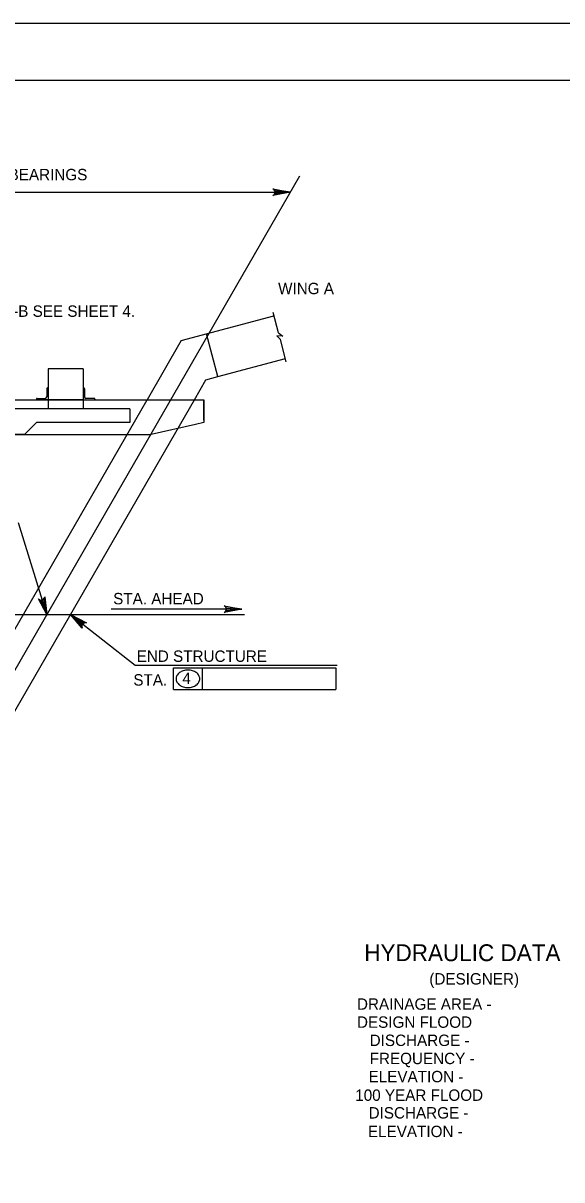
# Model space of a CAD drawing. Extents: x 638268 to 640277, y 295465 to 298435.
# Drawn here: x 638750 to 638891.9, y 298131.1 to 298435.5 of the extents above; entities that cross this region are included whole.
import ezdxf

# ---------------------------------------------------------------- set-up
doc = ezdxf.new("R2010")
doc.units = 0
for name, color, linetype in [('2', 7, 'Continuous'), ('3', 7, 'Continuous'), ('4', 7, 'Continuous'), ('PLT-BNDY', 7, 'Continuous')]:
    doc.layers.add(name, color=color, linetype=linetype)

msp = doc.modelspace()

# ---------------------------------------------------------------- linework, layer by layer
at = {"layer": '2'}
for p, q in [((638475.46, 298420.46), (639261.46, 298420.46)), ((638791.62, 298351.94), (638816.03, 298358.48)), ((638801.25, 298342.47), (638798.24, 298353.71)), ((638791.62, 298351.94), (638782.63, 298336.37)), ((638801.25, 298342.47), (638819.04, 298347.24)), ((638765.78, 298344.46), (638756.54, 298344.46)), ((638756.54, 298344.46), (638756.54, 298333.98)), ((638765.78, 298344.46), (638765.78, 298333.98)), ((638795.06, 298336.37), (638798.1, 298341.63)), ((638798.1, 298341.63), (638801.25, 298342.47)), ((638756.18, 298339.28), (638756.18, 298337.1)), ((638756.36, 298339.46), (638756.54, 298339.46)), ((638756.54, 298339.46), (638756.54, 298336.37)), ((638765.96, 298339.46), (638765.78, 298339.46)), ((638765.78, 298339.46), (638765.78, 298336.37)), ((638766.14, 298339.28), (638766.14, 298337.1)), ((638650.43, 298336.37), (638797.52, 298336.37)), ((638718.45, 298225.2), (638782.63, 298336.37)), ((638730.88, 298225.2), (638795.06, 298336.37)), ((638753.45, 298336.55), (638753.45, 298336.37)), ((638756.54, 298336.37), (638753.45, 298336.37)), ((638753.63, 298336.73), (638755.81, 298336.73)), ((638765.78, 298336.37), (638756.54, 298336.37)), ((638765.78, 298336.37), (638768.87, 298336.37)), ((638768.69, 298336.73), (638766.5, 298336.73)), ((638768.87, 298336.55), (638768.87, 298336.37)), ((638797.52, 298330.99), (638797.52, 298336.37)), ((638797.52, 298336.37), (638797.52, 298330.34)), ((638778.1, 298333.98), (638650.25, 298333.98)), ((638778.1, 298333.98), (638778.1, 298330.34)), ((638750.37, 298327.25), (638753.46, 298330.34)), ((638778.1, 298330.34), (638753.46, 298330.34)), ((638795.35, 298329.86), (638783.67, 298327.25)), ((638797.52, 298330.34), (638795.35, 298329.86)), ((638632.81, 298327.25), (638783.67, 298327.25)), ((638750.37, 298327.25), (638729.59, 298327.25))]:
    msp.add_line(p, q, dxfattribs=at)
for centre, radius, start, end in [((638756.36, 298339.28), 0.182, 90, 179.9984), ((638765.96, 298339.28), 0.182, 0.0016, 90), ((638753.63, 298336.55), 0.182, 90, 179.9984), ((638755.81, 298337.1), 0.364, 270, 359.9984), ((638766.5, 298337.1), 0.364, 180.0016, 270), ((638768.69, 298336.55), 0.182, 0.0016, 90)]:
    msp.add_arc(centre, radius, start, end, dxfattribs=at)
at = {"layer": '3'}
for p, q in [((638691.03, 298166.95), (638822.86, 298395.29)), ((638817.24, 298353.94), (638815.81, 298359.28)), ((638816.78, 298353.21), (638817.71, 298352.2)), ((638818.34, 298353.12), (638816.78, 298353.21)), ((638817.24, 298353.94), (638818.34, 298353.12)), ((638819.27, 298346.37), (638817.71, 298352.2))]:
    msp.add_line(p, q, dxfattribs=at)
at = {"layer": '4'}
for p, q in [((638628.98, 298391), (638820.39, 298391)), ((638756.2, 298279.83), (638748.74, 298304.01)), ((638807.54, 298281.23), (638773.18, 298281.23)), ((638523.29, 298279.83), (638808.3, 298279.83)), ((638762.42, 298279.83), (638779.49, 298266.49)), ((638779.49, 298266.49), (638832.67, 298266.49)), ((638789.59, 298265.87), (638797.17, 298265.87)), ((638789.59, 298260.11), (638789.59, 298265.87)), ((638797.17, 298260.11), (638797.17, 298265.87)), ((638797.17, 298265.87), (638832.35, 298265.87)), ((638832.35, 298265.87), (638832.35, 298260.11)), ((638789.59, 298260.11), (638832.35, 298260.11))]:
    msp.add_line(p, q, dxfattribs=at)
for points in [[(638820.39, 298391), (638815.73, 298390.12), (638816.08, 298390.37), (638816.27, 298390.68), (638816.32, 298391), (638816.27, 298391.31), (638816.08, 298391.62), (638815.73, 298391.87), (638820.39, 298391), (638816.08, 298391.62), (638816.27, 298391.31), (638820.39, 298391), (638816.32, 298391), (638816.27, 298390.68), (638820.39, 298391), (638816.08, 298390.37)], [(638756.2, 298279.83), (638753.99, 298284.03), (638754.34, 298283.76), (638754.69, 298283.67), (638755.01, 298283.71), (638755.29, 298283.86), (638755.53, 298284.12), (638755.66, 298284.54), (638756.2, 298279.83), (638755.53, 298284.12), (638755.29, 298283.86), (638756.2, 298279.83), (638755.01, 298283.71), (638754.69, 298283.67), (638756.2, 298279.83), (638754.34, 298283.76)], [(638807.54, 298281.23), (638802.88, 298280.36), (638803.24, 298280.61), (638803.43, 298280.92), (638803.48, 298281.23), (638803.43, 298281.55), (638803.24, 298281.86), (638802.88, 298282.11), (638807.54, 298281.23), (638803.24, 298281.86), (638803.43, 298281.55), (638807.54, 298281.23), (638803.48, 298281.23), (638803.43, 298280.92), (638807.54, 298281.23), (638803.24, 298280.61)], [(638762.42, 298279.83), (638766.63, 298277.65), (638766.19, 298277.67), (638765.86, 298277.54), (638765.62, 298277.33), (638765.47, 298277.05), (638765.43, 298276.69), (638765.55, 298276.27), (638762.42, 298279.83), (638765.43, 298276.69), (638765.47, 298277.05), (638762.42, 298279.83), (638765.62, 298277.33), (638765.86, 298277.54), (638762.42, 298279.83), (638766.19, 298277.67)]]:
    msp.add_lwpolyline(points, dxfattribs=at)
msp.add_lwpolyline([(638755.8, 298282.8), (638754.86, 298282.51), (638756.2, 298279.83)], close=True, dxfattribs=at)
for centre, radius, start, end in [((638793.08, 298261.96), 3.23, 106.9552, 126.3544), ((638793.37, 298261.02), 4.22, 90, 106.9552), ((638793.37, 298261.02), 4.22, 73.0448, 90), ((638793.66, 298261.96), 3.23, 53.6456, 73.0448), ((638791.97, 298262.94), 1.71, 150.6308, 180), ((638791.97, 298262.94), 1.71, 180, 209.3692), ((638792.64, 298262.56), 2.49, 126.3544, 150.6308), ((638792.64, 298263.32), 2.49, 209.3692, 233.6456), ((638794.1, 298262.56), 2.49, 29.3692, 53.6456), ((638794.1, 298263.32), 2.49, 306.3544, 330.6308), ((638794.78, 298262.94), 1.71, 0, 29.3692), ((638794.78, 298262.94), 1.71, 330.6308, 0), ((638793.08, 298263.92), 3.23, 233.6456, 253.0448), ((638793.37, 298264.87), 4.22, 253.0448, 270), ((638793.37, 298264.87), 4.22, 270, 286.9552), ((638793.66, 298263.92), 3.23, 286.9552, 306.3544)]:
    msp.add_arc(centre, radius, start, end, dxfattribs=at)
at = {"layer": 'PLT-BNDY'}
msp.add_lwpolyline([(638435.46, 298435.46), (639276.46, 298435.46), (639276.46, 297841.46), (638435.46, 297841.46)], close=True, dxfattribs=at)

# ---------------------------------------------------------------- texts
at = {"layer": '4'}
for s, height, p in [('L TO L BEARINGS', 3, (638732.77, 298394.11)), ('WING A', 3, (638817.12, 298364.14)), ('FOR VIEW B-B SEE SHEET 4.', 3, (638723.72, 298358.18)), ('STA. AHEAD', 3, (638773.68, 298282.54)), ('END STRUCTURE', 3, (638779.87, 298267.4)), ('STA.', 3, (638779, 298261.16)), ('4', 3, (638791.92, 298261.59)), ('HYDRAULIC DATA', 4.4292, (638839.81, 298188.66)), ('(DESIGNER)', 3, (638856.95, 298182.5)), ('DRAINAGE AREA - ', 3, (638837.89, 298175.87)), ('DESIGN FLOOD  ', 3, (638837.89, 298171.12)), ('   DISCHARGE - ', 3, (638837.89, 298166.33)), ('   FREQUENCY - ', 3, (638837.89, 298161.56)), ('   ELEVATION - ', 3, (638837.61, 298156.79)), ('100 YEAR FLOOD', 3, (638837.44, 298151.9)), ('   DISCHARGE - ', 3, (638837.61, 298147.25)), ('   ELEVATION - ', 3, (638837.44, 298142.36))]:
    msp.add_text(s, height=height, dxfattribs=at).set_placement(p)

doc.saveas('drawing.dxf')
